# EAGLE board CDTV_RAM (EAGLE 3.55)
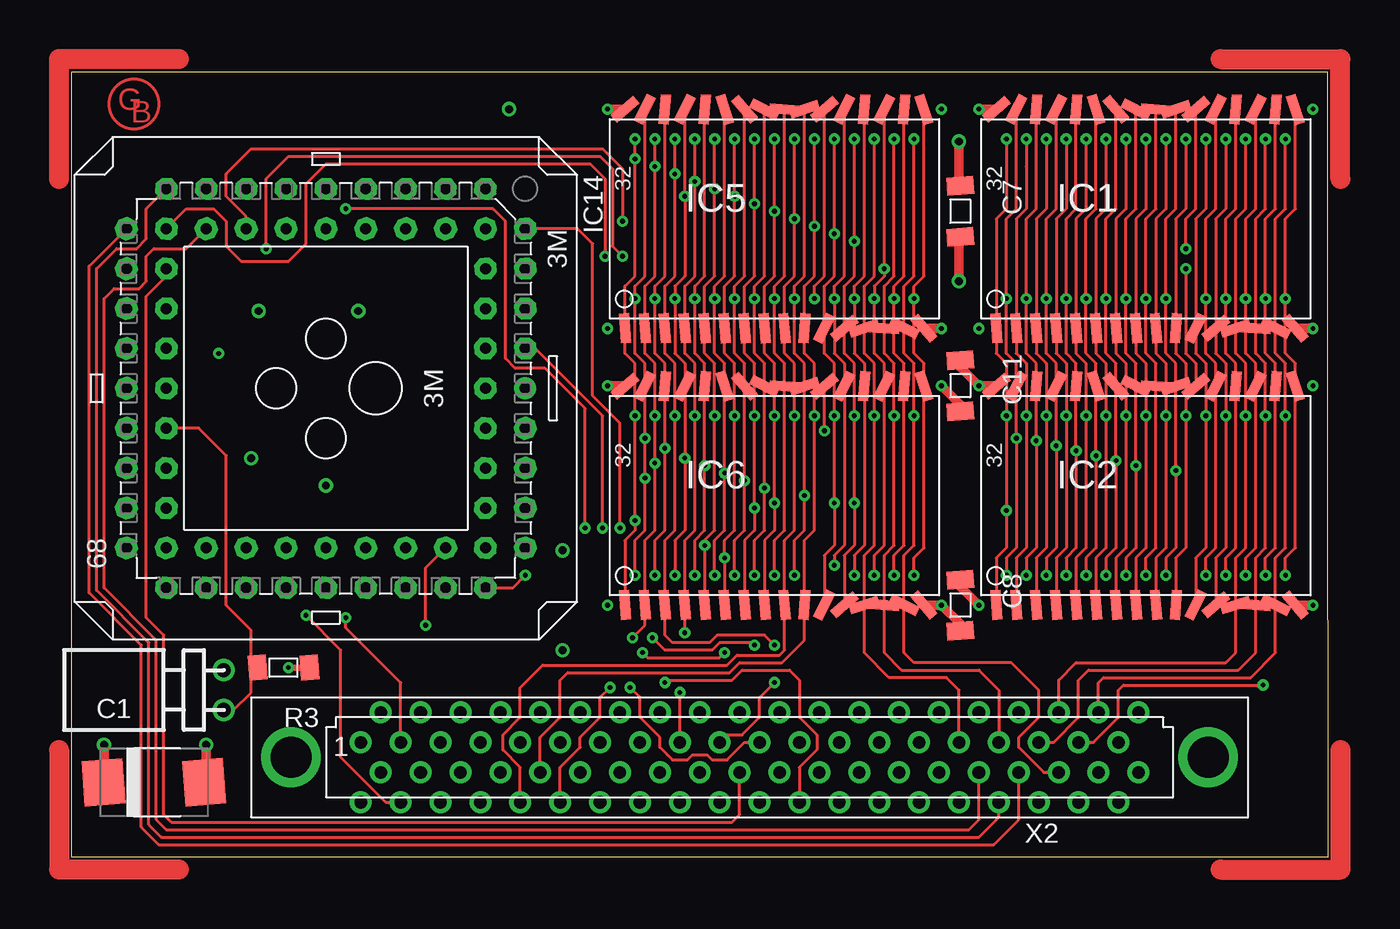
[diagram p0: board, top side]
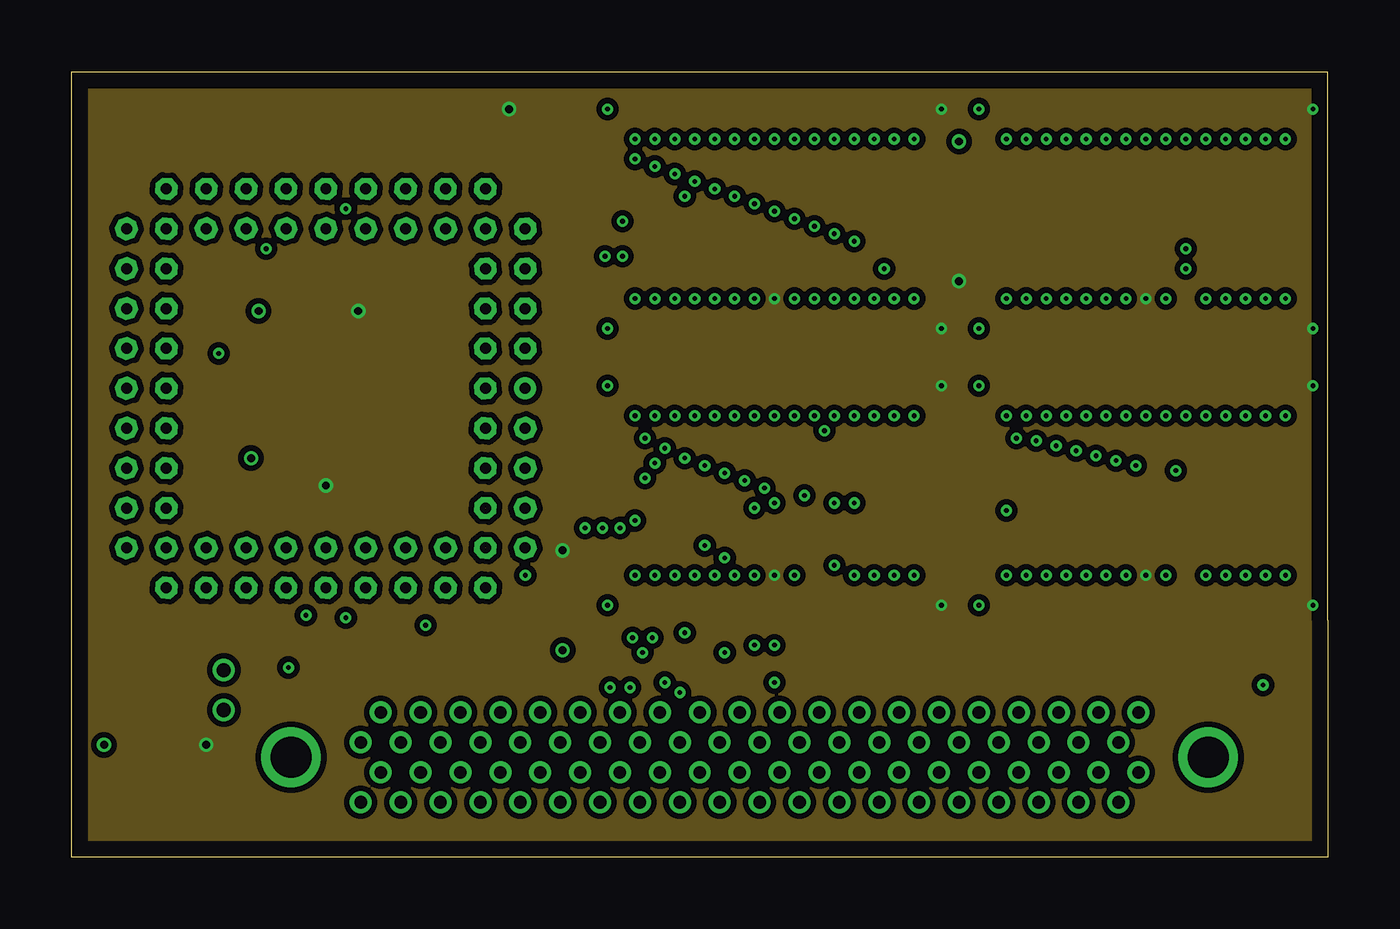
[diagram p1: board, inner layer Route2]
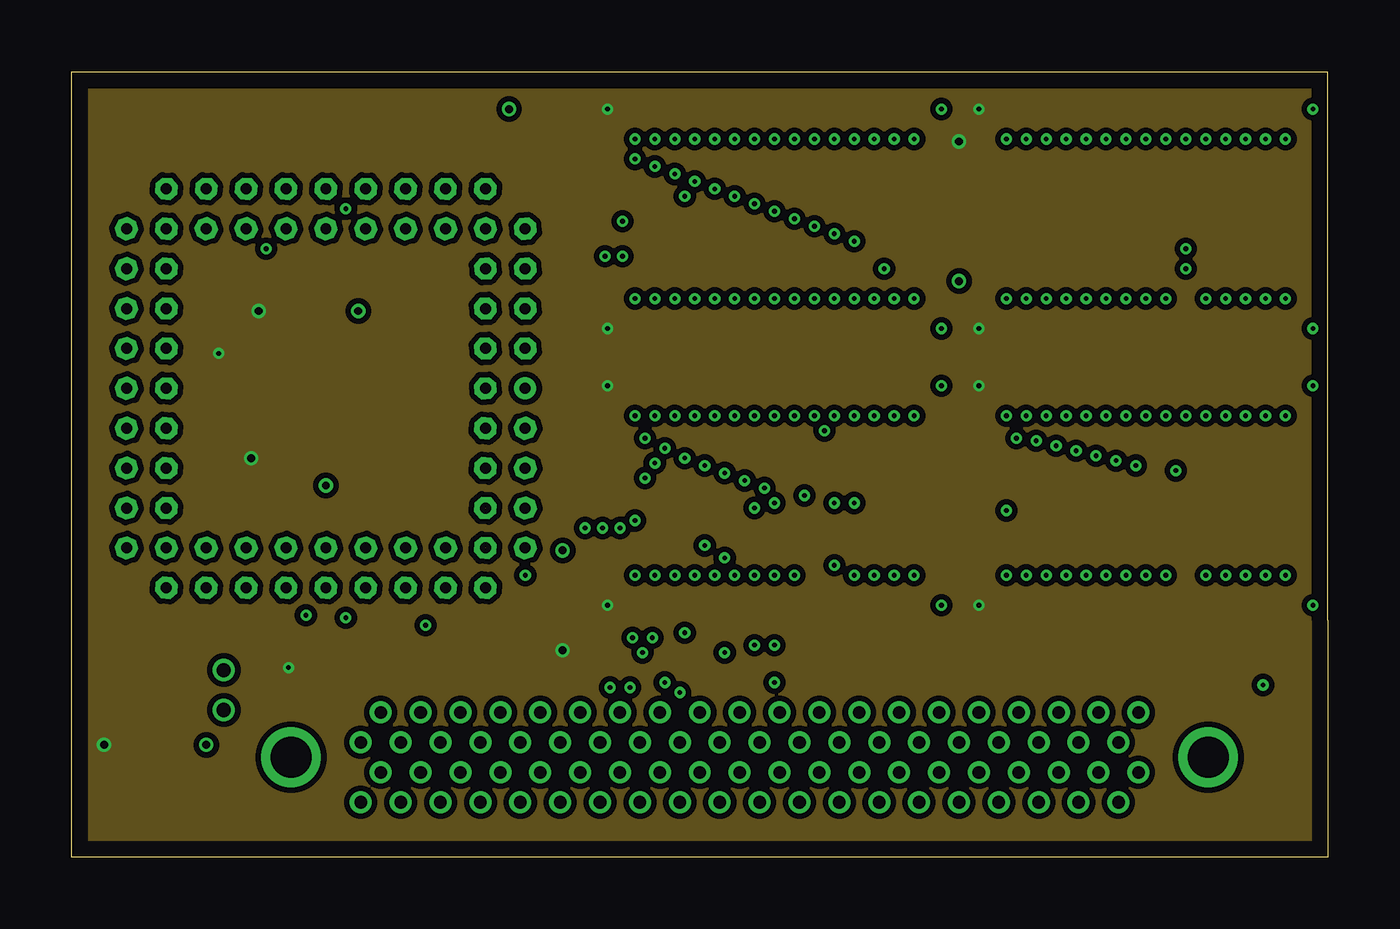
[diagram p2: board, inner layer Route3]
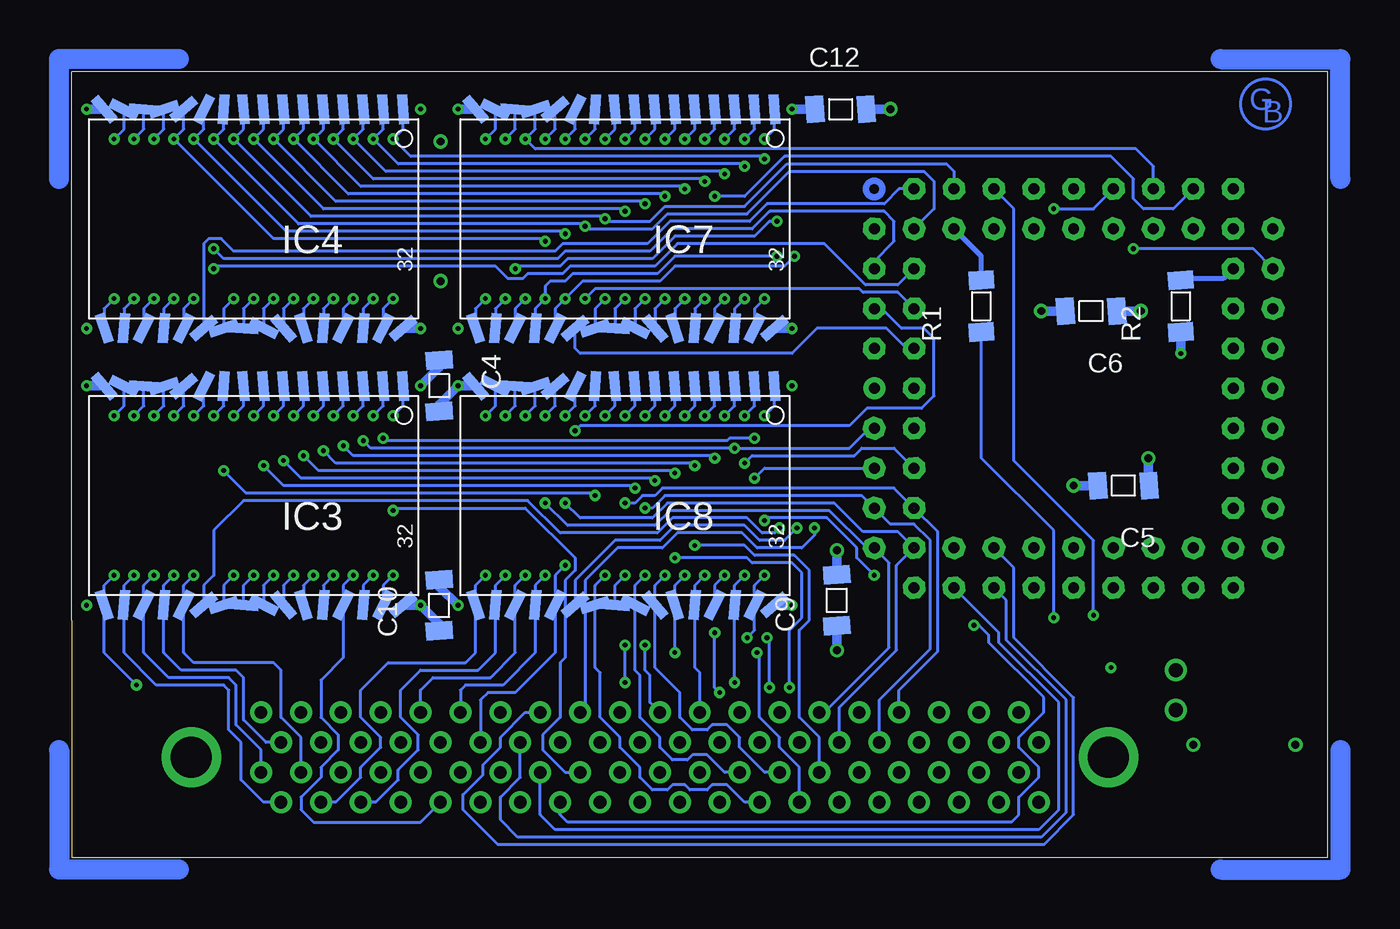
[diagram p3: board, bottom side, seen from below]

Size 80.01 x 50.01 mm. Coordinates in mm from the lower left corner, seen from the top.
Outline: 80.01,15.08 80.01,0 0,0 0,50.01 80.01,50.01 80.01,15.08
Copper layers used: Top, Route2, Route3, Bottom

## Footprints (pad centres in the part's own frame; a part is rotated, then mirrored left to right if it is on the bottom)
43 = smd 2.6 x 2.9 rotated 4.4:  3.207,0 | smd 2.6 x 2.9 rotated 4.3:  -3.207,0
06 = smd 1.143 x 1.702 rotated 4.4:  1.632,0 | smd 1.143 x 1.702 rotated 4.3:  -1.632,0
J32/5 = smd 0.635 x 1.905 rotated 49.5:  -9.525,6.966 | smd 0.635 x 1.905 rotated 27:  -8.255,6.966 | smd 0.635 x 1.905 rotated 4.5:  -6.985,6.966;  -6.985,-6.966 | smd 0.635 x 1.905 rotated 206.9:  -5.715,6.966 | smd 0.635 x 1.905 rotated 184.4:  -4.445,6.966 | smd 0.635 x 1.905 rotated 26.9:  4.445,6.966 | smd 0.635 x 1.905 rotated 49.4:  3.175,6.966 | smd 0.635 x 1.905 rotated 71.9:  1.905,6.966 | smd 0.635 x 1.905 rotated 94.4:  0.635,6.966 | smd 0.635 x 1.905 rotated 49.3:  4.445,-6.966 | smd 0.635 x 1.905 rotated 26.8:  3.175,-6.966 | smd 0.635 x 1.905 rotated 4.3:  1.905,-6.966;  -9.525,-6.966 | smd 0.635 x 1.905 rotated 5:  0.635,-6.966 | smd 0.635 x 1.905 rotated 4.7:  -4.445,-6.966;  -3.175,-6.966 | smd 0.635 x 1.905 rotated 4.6:  -5.715,-6.966 | smd 0.635 x 1.905 rotated 4.4:  -8.255,-6.966;  5.715,6.966 | smd 0.635 x 1.905 rotated 71.8:  5.715,-6.966 | smd 0.635 x 1.905 rotated 161.9:  -3.175,6.966 | smd 0.635 x 1.905 rotated 116.9:  -0.635,6.966 | smd 0.635 x 1.905 rotated 4.9:  -0.635,-6.966 | smd 0.635 x 1.905 rotated 139.4:  -1.905,6.966 | smd 0.635 x 1.905 rotated 4.8:  -1.905,-6.966 | smd 0.635 x 1.905 rotated 94.3:  6.985,-6.966 | smd 0.635 x 1.905 rotated 206.8:  6.985,6.966 | smd 0.635 x 1.905 rotated 116.8:  8.255,-6.966 | smd 0.635 x 1.905 rotated 139.3:  9.525,-6.966 | smd 0.635 x 1.905 rotated 184.3:  8.255,6.966 | smd 0.635 x 1.905 rotated 161.8:  9.525,6.966
CC68 = drill 0.7 pad 1.4 round:  0,12.7 | drill 0.7 pad 1.4 octagon:  0,10.16;  -2.54,12.7;  -2.54,10.16;  -5.08,12.7;  -5.08,10.16;  -7.62,12.7;  -7.62,10.16;  -10.16,12.7;  -12.7,10.16;  -10.16,10.16;  -12.7,7.62;  -10.16,7.62;  -12.7,5.08;  -10.16,5.08;  -12.7,2.54;  -10.16,2.54;  -12.7,0;  -10.16,0;  -12.7,-2.54;  -10.16,-2.54;  -12.7,-5.08;  -10.16,-5.08;  -12.7,-7.62;  -10.16,-7.62;  -12.7,-10.16;  -10.16,-12.7;  -10.16,-10.16;  -7.62,-12.7;  -7.62,-10.16;  -5.08,-12.7;  -5.08,-10.16;  -2.54,-12.7;  -2.54,-10.16;  0,-12.7;  0,-10.16;  2.54,-12.7;  2.54,-10.16;  5.08,-12.7;  5.08,-10.16;  7.62,-12.7;  7.62,-10.16;  10.16,-12.7;  12.7,-10.16;  10.16,-10.16;  12.7,-7.62;  10.16,-7.62;  12.7,-5.08;  10.16,-5.08;  12.7,-2.54;  10.16,-2.54;  12.7,0;  10.16,0;  12.7,2.54;  10.16,2.54;  12.7,5.08;  10.16,5.08;  12.7,7.62;  10.16,7.62;  12.7,10.16;  10.16,12.7;  10.16,10.16;  7.62,12.7;  7.62,10.16;  5.08,12.7;  5.08,10.16;  2.54,12.7;  2.54,10.16
04 = smd 1.16 x 1.6 rotated 4.4:  1.651,0 | smd 1.16 x 1.6 rotated 4.3:  -1.651,0
UECK-J = drill 0.9 pad 1.422 round:  -1.27,5.08;  1.27,5.08
TV-80 = drill 2.6 pad 3.8 round: 1 29.21,0; 2 -29.21,0 | drill 0.8 pad 1.4 round:  24.765,-0.953;  24.765,2.857;  23.495,-2.857;  23.495,0.953;  22.225,-0.953;  22.225,2.857;  20.955,-2.857;  20.955,0.953;  19.685,-0.953;  19.685,2.857;  18.415,-2.857;  18.415,0.953;  17.145,-0.953;  17.145,2.857;  15.875,-2.857;  15.875,0.953;  14.605,-0.953;  14.605,2.857;  13.335,-2.857;  13.335,0.953;  12.065,-0.953;  12.065,2.857;  10.795,-2.857;  10.795,0.953;  9.525,-0.953;  9.525,2.857;  8.255,-2.857;  8.255,0.953;  6.985,-0.953;  6.985,2.857;  5.715,-2.857;  5.715,0.953;  4.445,-0.953;  4.445,2.857;  3.175,-2.857;  3.175,0.953;  1.905,-0.953;  1.905,2.857;  0.635,-2.857;  0.635,0.953;  -0.635,-0.953;  -0.635,2.857;  -1.905,-2.857;  -1.905,0.953;  -3.175,-0.953;  -3.175,2.857;  -4.445,-2.857;  -4.445,0.953;  -5.715,-0.953;  -5.715,2.857;  -6.985,-2.857;  -6.985,0.953;  -8.255,-0.953;  -8.255,2.857;  -9.525,-2.857;  -9.525,0.953;  -10.795,-0.953;  -10.795,2.857;  -12.065,-2.857;  -12.065,0.953;  -13.335,-0.953;  -13.335,2.857;  -14.605,-2.857;  -14.605,0.953;  -15.875,-0.953;  -15.875,2.857;  -17.145,-2.857;  -17.145,0.953;  -18.415,-0.953;  -18.415,2.857;  -19.685,-2.857;  -19.685,0.953;  -20.955,-0.953;  -20.955,2.857;  -22.225,-2.857;  -22.225,0.953;  -23.495,-0.953;  -23.495,2.857;  -24.765,-2.857;  -24.765,0.953

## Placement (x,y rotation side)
C1  47uF  [43]  5.24,4.76 0 top
C4  100nF  [06]  56.59,30 270 bottom
C5  100nF  [06]  13.02,23.65 180 bottom
C6  100nF  [06]  15.08,34.77 180 bottom
C7  100nF  [06]  56.59,41.12 270 top
C8  100nF  [06]  56.59,16.03 270 top
C9  100nF  [06]  31.27,16.35 90 bottom
C10  100nF  [06]  56.59,16.03 90 bottom
C11  100nF  [06]  56.59,30 270 top
C12  100nF  [06]  31.04,47.63 0 bottom
IC1  628512  [J32/5]  68.42,40.64 0 top
IC2  628512  [J32/5]  68.42,23.02 0 top
IC3  628512  [J32/5]  68.42,23.02 180 bottom
IC4  628512  [J32/5]  68.42,40.64 180 bottom
IC5  628512  [J32/5]  44.77,40.64 0 top
IC6  628512  [J32/5]  44.77,23.02 0 top
IC7  628512  [J32/5]  44.77,40.64 180 bottom
IC8  628512  [J32/5]  44.77,23.02 180 bottom
IC14  LSI1024  [CC68]  16.19,29.85 270 top
R1  332R  [04]  22.07,35.08 90 bottom
R2  4k7  [04]  9.37,35.08 90 bottom
R3  4k7  [04]  13.49,12.07 180 top
S1  JUM-BR  [UECK-J]  4.6,10.64 270 top
U$2  []  3.97,47.94 0 top
U$3  [LO-2]  80.17,-0.16 180 top
U$4  [LO-2]  -0.16,-0.16 90 top
U$5  [LO-2]  80.17,50.16 270 top
U$6  []  3.97,47.94 0 bottom
U$9  [LO-2]  -0.16,50.17 0 top
X2  CDTV-80  [TV-80]  43.18,6.35 180 top

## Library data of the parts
C1 C4-C12 R1-R3 = SMD
IC1-IC8 = SMD-IC
IC14 = DIL-IC
S1 X2 = Stecker
U$2-U$6 U$9 = MARKS

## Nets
A1: IC1. IC2. IC3. IC4. IC5. IC6. IC7. IC8. IC14. X2.
A2: IC1. IC2. IC3. IC4. IC5. IC6. IC7. IC8. IC14. X2.
A3: IC1. IC2. IC3. IC4. IC5. IC6. IC7. IC8. IC14. X2.
A4: IC1. IC2. IC3. IC4. IC5. IC6. IC7. IC8. IC14. X2.
A5: IC1. IC2. IC3. IC4. IC5. IC6. IC7. IC8. IC14. X2.
A6: IC1. IC2. IC3. IC4. IC5. IC6. IC7. IC8. IC14. X2.
A7: IC1. IC2. IC3. IC4. IC5. IC6. IC7. IC8. X2.
A8: IC1. IC2. IC3. IC4. IC5. IC6. IC7. IC8. X2.
A9: IC1. IC2. IC3. IC4. IC5. IC6. IC7. IC8. X2.
A10: IC1. IC2. IC3. IC4. IC5. IC6. IC7. IC8. X2.
A11: IC1. IC2. IC3. IC4. IC5. IC6. IC7. IC8. X2.
A12: IC1. IC2. IC3. IC4. IC5. IC6. IC7. IC8. X2.
A13: IC1. IC2. IC3. IC4. IC5. IC6. IC7. IC8. X2.
A14: IC1. IC2. IC3. IC4. IC5. IC6. IC7. IC8. X2.
A15: IC1. IC2. IC3. IC4. IC5. IC6. IC7. IC8. X2.
A16: IC1. IC2. IC3. IC4. IC5. IC6. IC7. IC8. IC14. X2.
A17: IC1. IC2. IC3. IC4. IC5. IC6. IC7. IC8. IC14. X2.
A18: IC1. IC2. IC3. IC4. IC5. IC6. IC7. IC8. IC14. X2.
A19: IC1. IC2. IC3. IC4. IC5. IC6. IC7. IC8. IC14. X2.
A20: IC14. X2.
A21: IC14. X2.
A22: IC14. X2.
A23: IC14. X2.
AS: IC14. X2.
BERR: IC14. R2. X2.
CE0: IC1. IC14.
CE1: IC2. IC14.
CE2: IC3. IC14.
CE3: IC4. IC14.
CE4: IC5. IC14.
CE5: IC6. IC14.
CE6: IC7. IC14.
CE7: IC8. IC14.
CONFIN: IC14. X2.
CONFOUT: IC14. R1.
D0: IC1. IC2. IC3. IC4. X2.
D1: IC1. IC2. IC3. IC4. X2.
D2: IC1. IC2. IC3. IC4. X2.
D3: IC1. IC2. IC3. IC4. X2.
D4: IC1. IC2. IC3. IC4. X2.
D5: IC1. IC2. IC3. IC4. X2.
D6: IC1. IC2. IC3. IC4. X2.
D7: IC1. IC2. IC3. IC4. X2.
D8: IC5. IC6. IC7. IC8. X2.
D9: IC5. IC6. IC7. IC8. X2.
D10: IC5. IC6. IC7. IC8. X2.
D11: IC5. IC6. IC7. IC8. X2.
D12: IC5. IC6. IC7. IC8. IC14. X2.
D13: IC5. IC6. IC7. IC8. IC14. X2.
D14: IC5. IC6. IC7. IC8. IC14. X2.
D15: IC5. IC6. IC7. IC8. IC14. X2.
GND: C1. C4. C5. C6. C7. C8. C9. C10. C11. C12. IC1. IC2. IC3. IC4. IC5. IC6. IC7. IC8. IC14. S1. X2.
LDS: IC14. X2.
N$1: R1. X2.
OE: IC14.
RAMEN: IC14. R3. S1.
RST: IC14. X2.
RW: IC1. IC2. IC3. IC4. IC5. IC6. IC7. IC8. IC14. X2.
UDS: IC14. X2.
VCC: C1. C4. C5. C6. C7. C8. C9. C10. C11. C12. IC1. IC2. IC3. IC4. IC5. IC6. IC7. IC8. IC14. R2. R3. X2.

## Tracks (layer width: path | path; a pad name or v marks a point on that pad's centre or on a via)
A1  (via drill 0.3 pad 0.6)
  Top 0.2: v73.5,45.72 73.5,41.28 72.87,40.64 72.87,33.67 72.87,32.07 73.5,31.43 v73.5,28.1 73.5,19.69 72.87,19.05 72.87,16.05 | 49.85,36.99 49.21,36.35 49.21,33.67 49.21,32.07 49.85,31.43 v49.85,28.1 49.85,27.94 | 49.21,16.05 49.21,19.21 49.85,19.84 | v49.85,45.72 | v49.85,45.72 v49.85,39.21 49.85,36.99 | 49.85,36.99 | 49.85,27.94 | 49.85,27.94 v49.85,22.54 49.85,19.84 | 49.85,19.84
  Bottom 0.2: 72.87,47.61 72.87,46.36 v73.5,45.72 67.15,39.37 50.01,39.37 v49.85,39.21 | 72.87,29.99 72.87,28.73 v73.5,28.1 | 49.21,47.61 49.21,46.36 v49.85,45.72 | 49.21,29.99 49.21,28.73 v49.85,28.1 | 28.89,19.69 29.37,19.69 31.75,22.07 41.91,22.07 42.86,21.11 48.42,21.11 v49.85,22.54 | 32.38,9.21 32.07,9.21 27.94,13.34 27.94,18.73 28.89,19.69 | 28.89,19.69 | 28.89,19.69 | 28.89,19.69
A2  (via drill 0.3 pad 0.6)  (1 unrouted)
  Top 0.2: v72.23,45.72 72.23,41.28 71.6,40.64 71.6,33.67 71.6,32.07 72.23,31.43 v72.23,28.1 72.23,19.69 71.6,19.05 71.6,16.05 | 48.58,36.99 47.94,36.35 47.94,33.67 47.94,32.07 48.58,31.43 v48.58,28.1 | 47.94,16.05 47.94,19.21 48.58,19.84 | v48.58,45.72 | v48.58,45.72 v48.58,39.69 48.58,36.99 | 48.58,36.99 | v48.58,28.1 | v48.58,28.1 v48.58,22.54 48.58,19.84 | 48.58,19.84
  Bottom 0.2: 71.6,47.61 71.6,46.36 v72.23,45.72 66.36,39.85 48.74,39.85 v48.58,39.69 | 71.6,29.99 71.6,28.73 v72.23,28.1 | 47.94,47.61 47.94,46.36 v48.58,45.72 | 47.94,29.99 47.94,28.73 v48.58,28.1 | 26.35,19.69 27.38,20.72 29.61,20.72 31.43,22.54 42.07,22.54 43.02,21.59 47.62,21.59 v48.58,22.54 | 31.11,7.3 31.11,9.53 27.46,13.18 27.46,18.57 26.35,19.69
A3  (via drill 0.3 pad 0.6)
  Top 0.2: v70.96,45.72 70.96,41.28 70.33,40.64 70.33,33.67 70.33,32.07 70.96,31.43 v70.96,28.1 70.96,19.69 70.33,19.05 70.33,16.05 | 47.31,36.99 46.67,36.35 46.67,33.67 46.67,32.07 47.31,31.43 v47.31,28.1 47.31,20.8 46.67,20.16 46.67,16.05 46.67,13.81 45.24,12.38 42.54,12.38 41.91,11.75 31.59,11.75 31.11,11.27 31.11,8.89 29.84,7.62 29.84,5.4 | v47.31,45.72 | v47.31,45.72 v47.31,40.16 47.31,36.99 | 47.31,36.99
  Bottom 0.2: 70.33,47.61 70.33,46.36 v70.96,45.72 65.56,40.32 47.47,40.32 v47.31,40.16 47.15,40.01 43.02,40.01 42.07,40.96 36.99,40.96 34.29,43.66 25.72,43.66 25.08,43.02 25.08,41.28 26.35,40.01 | 70.33,29.99 70.33,28.73 v70.96,28.1 | 46.67,47.61 46.67,46.36 v47.31,45.72 | 46.67,29.99 46.67,28.73 v47.31,28.1 | 26.35,40.01 | 26.35,40.01
A4  (via drill 0.3 pad 0.6)
  Top 0.2: v69.69,45.72 69.69,41.28 69.06,40.64 69.06,33.67 69.06,32.07 69.69,31.43 v69.69,28.1 69.69,19.69 69.06,19.05 69.06,16.05 | v46.04,45.72 | v46.04,45.72 v46.04,40.64 46.04,36.99 45.4,36.35 45.4,33.67 45.4,32.07 46.04,31.43 v46.04,28.1 46.04,20.8 45.4,20.16 45.4,16.05 45.4,13.18 45.08,12.86 42.39,12.86 41.75,12.22 30,12.22 28.57,10.8 28.57,8.89 27.46,7.78 27.46,6.83 28.57,5.72 28.57,3.49
  Bottom 0.2: 69.06,47.61 69.06,46.36 v69.69,45.72 64.77,40.8 46.2,40.8 v46.04,40.64 45.88,40.48 43.18,40.48 42.23,41.43 37.15,41.43 34.45,44.13 24.29,44.13 23.81,43.66 23.81,42.55 | 69.06,29.99 69.06,28.73 v69.69,28.1 | 45.4,47.61 45.4,46.36 v46.04,45.72 | 45.4,29.99 45.4,28.73 v46.04,28.1 | 23.81,42.55 | 23.81,42.55
A5  (via drill 0.3 pad 0.6)  (1 unrouted)
  Top 0.2: v68.42,45.72 68.42,41.28 67.79,40.64 67.79,33.67 67.79,32.07 68.42,31.43 v68.42,28.1 68.42,19.69 67.79,19.05 67.79,16.05 | 44.77,36.99 44.13,36.35 44.13,33.67 44.13,32.07 44.77,31.43 v44.77,28.1 v44.77,22.54 44.77,20.8 44.13,20.16 44.13,16.05 | v44.77,45.72 | v44.77,45.72 v44.77,41.12 44.77,36.99 | 44.77,36.99
  Bottom 0.2: 67.79,47.61 67.79,46.36 v68.42,45.72 63.98,41.28 44.93,41.28 v44.77,41.12 | 67.79,29.99 67.79,28.73 v68.42,28.1 | 44.13,47.61 44.13,46.36 v44.77,45.72 | 44.13,29.99 44.13,28.73 v44.77,28.1 | 26.35,22.23 27.62,23.5 42.39,23.5 42.86,23.02 43.66,23.02 44.13,22.54 v44.77,22.54 | 26.35,22.23 24.84,20.72 24.84,13.1 27.3,10.64 27.3,9.21 | 27.3,9.21
A6  (via drill 0.3 pad 0.6)
  Top 0.2: v67.15,45.72 67.15,41.28 66.52,40.64 66.52,33.67 66.52,32.07 67.15,31.43 v67.15,28.1 67.15,19.69 66.52,19.05 66.52,16.05 | 43.5,36.99 42.86,36.35 42.86,33.67 42.86,32.07 43.5,31.43 v43.5,28.1 43.5,27.94 | 42.86,16.05 42.86,20.16 43.5,20.8 | v43.5,45.72 | v43.5,45.72 v43.5,41.59 43.5,36.99 | 43.5,36.99 | 43.5,27.94 | 43.5,27.94 v43.5,22.23 43.5,20.8 | 43.5,20.8
  Bottom 0.2: 66.52,47.61 66.52,46.36 v67.15,45.72 63.18,41.75 43.66,41.75 v43.5,41.59 | 66.52,29.99 66.52,28.73 v67.15,28.1 | 42.86,47.61 42.86,46.36 v43.5,45.72 | 42.86,29.99 42.86,28.73 v43.5,28.1 | 28.57,7.3 | 28.57,7.3 28.57,10 25.32,13.26 25.32,20.16 26.35,21.19 27.86,21.19 28.89,22.23 29.69,23.02 42.23,23.02 43.02,22.23 v43.5,22.23
A7  (via drill 0.3 pad 0.6)
  Top 0.2: v65.88,45.72 65.88,41.28 65.25,40.64 65.25,33.67 65.25,32.07 65.88,31.43 v65.88,28.1 65.88,19.69 65.25,19.05 65.25,16.05 | 42.23,36.99 41.59,36.35 41.59,33.67 41.59,32.07 42.23,31.43 v42.23,28.1 42.23,20.8 41.59,20.16 v41.59,19.05 41.59,16.03 | 41.59,16.03 | 41.59,16.03 41.59,16.05 | 42.23,36.99 | 42.23,36.99 v42.23,42.07 v42.23,45.72 | v42.23,45.72 | v34.29,10.8 33.65,10.16 33.65,8.89 32.38,7.62 32.38,6.99 31.11,5.72 31.11,3.49 | 31.11,3.49 | 41.59,16.03
  Bottom 0.2: 65.25,47.61 65.25,46.36 v65.88,45.72 62.39,42.23 42.39,42.23 v42.23,42.07 | 65.25,29.99 65.25,28.73 v65.88,28.1 | 41.59,47.61 41.59,46.36 v42.23,45.72 | 41.59,29.99 41.59,28.73 v42.23,28.1 | v34.29,10.8 34.29,14.45 33.5,15.24 33.5,18.1 34.13,18.73 36.67,18.73 36.99,19.05 v41.59,19.05
A8  (via drill 0.3 pad 0.6)
  Top 0.2: v64.61,45.72 64.61,41.28 63.98,40.64 63.98,33.67 63.98,32.07 64.61,31.43 v64.61,28.1 64.61,19.69 63.98,19.05 63.98,16.05 | 40.96,36.99 40.32,36.35 40.32,33.67 40.32,33.66 | 40.32,33.66 | 40.32,33.66 40.32,32.07 40.96,31.43 v40.96,28.1 40.96,20.8 40.32,20.16 v40.32,19.84 40.32,16.05 40.32,16.03 | 40.96,36.99 | 40.96,36.99 v40.96,42.55 v40.96,45.72 | v40.96,45.72
  Bottom 0.2: 63.98,47.61 63.98,46.36 v64.61,45.72 61.59,42.7 41.12,42.7 v40.96,42.55 | 63.98,29.99 63.98,28.73 v64.61,28.1 | 40.32,47.61 40.32,46.36 v40.96,45.72 | 40.32,29.99 40.32,28.73 v40.96,28.1 | 32.38,5.4 32.38,7.62 33.65,8.89 33.65,14.45 33.02,15.08 33.02,18.26 33.97,19.21 36.51,19.21 37.15,19.84 v40.32,19.84
A9  (via drill 0.3 pad 0.6)
  Top 0.2: 65.25,47.61 65.25,41.28 64.61,40.64 v64.61,35.56 64.61,32.07 65.25,31.43 65.25,29.99 65.25,29.85 v65.25,25.56 65.25,19.69 | 65.25,19.69 64.61,19.05 v64.61,17.94 | 41.59,47.61 41.59,36.99 40.96,36.35 v40.96,35.56 40.96,32.07 41.59,31.43 41.59,29.99 41.59,30 | 41.59,20.8 40.96,20.16 v40.96,17.94 | 65.25,19.69 | 41.59,20.8 | 41.59,20.8 v41.59,24.45 41.59,30 | 41.59,20.8 | 41.59,30 | 41.59,30 | 41.27,12.7 | 41.27,12.7 v41.59,13.02 | v36.35,13.02 36.67,12.7 41.27,12.7
  Bottom 0.2: 65.25,33.67 65.25,34.93 v64.61,35.56 | 65.25,16.05 65.25,17.3 v64.61,17.94 | 41.59,33.67 41.59,34.93 v40.96,35.56 | v40.96,17.94 41.59,17.3 41.59,16.05 41.59,16.03 | v41.59,24.45 41.75,24.61 64.29,24.61 v65.25,25.56 | 33.65,3.49 33.65,5.72 34.92,6.99 34.92,7.62 36.19,8.89 36.19,12.86 v36.35,13.02 | 41.59,16.03 | v41.59,13.02 41.59,16.03 | v36.35,13.02
A10  (via drill 0.3 pad 0.6)
  Top 0.2: 66.52,47.61 66.52,41.28 65.88,40.64 v65.88,35.56 65.88,32.07 66.52,31.43 66.52,29.99 66.52,29.85 v66.52,25.24 66.52,19.69 | 66.52,19.69 65.88,19.05 v65.88,17.94 | 42.86,47.61 42.86,36.99 42.23,36.35 v42.23,35.56 42.23,32.07 42.86,31.43 42.86,29.99 42.86,30 v42.86,23.97 42.86,20.8 42.23,20.16 v42.23,17.94 | 66.52,19.69
  Bottom 0.2: 66.52,33.67 66.52,34.93 v65.88,35.56 | 66.52,16.05 66.52,17.3 v65.88,17.94 | 42.86,33.67 42.86,34.93 v42.23,35.56 | v42.23,17.94 42.86,17.3 42.86,16.05 42.86,12.07 41.27,10.48 41.27,8.89 40.48,8.1 39.53,8.1 39.21,8.41 38.26,8.41 37.46,7.62 37.46,6.99 35.88,5.4 34.92,5.4 | v42.86,23.97 43.02,24.13 65.4,24.13 v66.52,25.24 | 34.92,5.4
A11  (via drill 0.3 pad 0.6)
  Top 0.2: 70.33,47.61 70.33,41.28 69.69,40.64 v69.69,35.56 69.69,32.07 70.33,31.43 70.33,29.99 70.33,30 v70.33,24.61 70.33,19.69 69.69,19.05 v69.69,17.94 | 46.67,47.61 46.67,36.99 46.04,36.35 v46.04,35.56 46.04,32.07 46.67,31.43 46.67,29.99 46.67,30 v46.67,23.02 46.67,20.8 46.04,20.16 v46.04,17.94
  Bottom 0.2: 70.33,33.67 70.33,34.93 v69.69,35.56 | 70.33,16.05 70.33,17.3 v69.69,17.94 | 46.67,33.67 46.67,34.93 v46.04,35.56 | v46.04,17.94 46.67,17.3 46.67,16.05 46.67,16.03 46.67,12.07 46.35,11.75 46.35,8.89 45.08,7.62 45.08,6.99 43.81,5.72 43.81,5.08 43.02,4.29 42.07,4.29 41.75,4.6 40.96,4.6 40.64,4.29 39.53,4.29 39.21,4.6 38.26,4.6 37.15,3.49 36.19,3.49 | v46.67,23.02 46.83,23.18 68.9,23.18 v70.33,24.61
A12  (via drill 0.3 pad 0.6)
  Top 0.2: 67.79,47.61 67.79,41.28 67.15,40.64 v67.15,35.56 67.15,32.07 67.79,31.43 67.79,29.99 67.79,30 v67.79,24.92 67.79,19.69 | 67.79,19.69 67.15,19.05 v67.15,17.94 | 44.13,47.61 44.13,36.99 43.5,36.35 v43.5,35.56 43.5,32.07 44.13,31.43 44.13,29.99 44.13,30 | 44.13,20.8 43.5,20.16 v43.5,17.94 | 67.79,19.69 | 44.13,20.8 | 44.13,20.8 v44.13,23.5 44.13,30 | 44.13,30
  Bottom 0.2: 67.79,33.67 67.79,34.93 v67.15,35.56 | 67.79,16.05 67.79,17.3 v67.15,17.94 | 44.13,33.67 44.13,34.93 v43.5,35.56 | v43.5,17.94 44.13,17.3 44.13,16.05 44.13,16.03 | v44.13,23.5 44.29,23.65 66.52,23.65 v67.79,24.92 | 37.46,5.4 38.42,5.4 39.53,6.51 40.48,6.51 40.8,6.19 41.75,6.19 42.54,6.99 42.54,7.62 43.81,8.89 43.81,11.59 44.13,11.91 44.13,16.03 | 44.13,16.03
A13  (via drill 0.3 pad 0.6)
  Top 0.2: 62.71,16.05 62.71,19.05 63.34,19.69 v63.34,28.1 63.34,31.43 62.71,32.07 62.71,33.67 62.71,40.64 63.34,41.28 63.34,41.91 v63.34,45.72 | 39.69,36.99 39.05,36.35 39.05,33.67 39.05,32.07 39.69,31.43 v39.69,28.1 39.69,20.8 39.05,20.16 39.05,16.03 | 39.05,16.03 | 39.05,16.03 39.05,16.05 | v39.69,45.72 | v39.69,45.72 v39.69,43.02 39.69,36.99 | 39.69,36.99 | v39.05,14.29 39.05,16.03 | 38.73,7.3 | 38.73,7.3 v38.73,10.48
  Bottom 0.2: 62.71,47.61 62.71,46.36 v63.34,45.72 60.8,43.18 39.85,43.18 v39.69,43.02 | 62.71,29.99 62.71,28.73 v63.34,28.1 | 39.05,47.61 39.05,46.36 v39.69,45.72 | 39.05,29.99 39.05,28.73 v39.69,28.1 | v39.05,14.29 39.05,10.8 v38.73,10.48
A14  (via drill 0.3 pad 0.6)
  Top 0.2: 63.98,47.61 63.98,41.28 63.34,40.64 v63.34,35.56 63.34,32.07 63.98,31.43 63.98,29.99 63.98,30 v63.98,25.88 63.98,19.69 | 63.98,19.69 63.34,19.05 v63.34,17.94 | 40.32,47.61 40.32,36.99 39.69,36.35 v39.69,35.56 39.69,32.07 40.32,31.43 40.32,29.99 40.32,30 v40.32,24.92 40.32,20.8 39.69,20.16 v39.69,17.94 | 63.98,19.69
  Bottom 0.2: 63.98,33.67 63.98,34.93 v63.34,35.56 | 63.98,16.05 63.98,17.3 v63.34,17.94 | 40.32,33.67 40.32,34.93 v39.69,35.56 | v39.69,17.94 40.32,17.3 40.32,16.05 40.32,12.07 40,11.75 40,9.21 | v40.32,24.92 40.48,25.08 63.18,25.08 v63.98,25.88 | 40,9.21
A15  (via drill 0.3 pad 0.6)
  Top 0.2: 62.07,41.28 61.44,40.64 61.44,33.67 61.44,32.07 62.07,31.43 v62.07,28.1 62.07,19.69 61.44,19.05 61.44,16.05 | 38.42,36.99 37.78,36.35 37.78,33.67 37.78,33.66 | 37.78,33.66 | 37.78,33.66 37.78,32.07 38.42,31.43 v38.42,28.1 38.42,20.8 37.78,20.16 37.78,16.05 37.78,14.13 38.26,13.65 40.64,13.65 41.12,14.13 44.13,14.13 v44.77,13.49 | v62.07,45.72 | 62.07,41.28 | v62.07,45.72 62.07,41.28 | v38.42,45.72 | v38.42,45.72 v38.42,43.5 38.42,36.99 | 38.42,36.99 | v44.77,11.11 43.81,10.16 43.81,8.89 42.7,7.78 41.75,7.78 41.27,7.3 | 41.27,7.3
  Bottom 0.2: 61.44,47.61 61.44,46.36 v62.07,45.72 60.01,43.66 38.58,43.66 v38.42,43.5 | 61.44,29.99 61.44,28.73 v62.07,28.1 | 37.78,47.61 37.78,46.36 v38.42,45.72 | 37.78,29.99 37.78,28.73 v38.42,28.1 | v44.77,11.11 v44.77,13.49
A16  (via drill 0.3 pad 0.6)
  Top 0.2: 60.17,41.28 59.53,40.64 v59.53,35.56 59.53,32.07 60.17,31.43 60.17,29.99 60.17,29.85 v60.17,26.67 60.17,19.69 | 60.17,19.69 59.53,19.05 v59.53,17.94 | 36.51,47.61 36.51,36.99 35.88,36.35 v35.88,35.56 35.88,32.07 36.51,31.43 36.51,29.99 | v35.88,17.94 35.88,20.16 36.51,20.8 | 36.51,30 | 36.51,29.99 36.51,30 | 60.17,47.61 60.17,47.63 60.17,41.28 | 60.17,41.28 | 60.17,19.69 | 36.51,29.85 | 36.51,29.85 36.51,29.99 | 36.51,29.85 v36.51,26.67 36.51,24.45 v36.51,24.13 36.51,20.8 | 36.51,20.8 | 36.51,20.8 | 36.51,20.8 | v43.5,13.49 43.34,13.65 41.27,13.65 40.8,13.18 37.78,13.18 v36.99,13.97 | v36.99,13.97
  Bottom 0.2: 60.17,33.67 60.17,34.93 v59.53,35.56 | 60.17,16.05 60.17,17.3 v59.53,17.94 | 36.51,33.67 36.51,34.93 v35.88,35.56 | v35.88,17.94 36.51,17.3 36.51,16.05 36.51,16.03 | 28.89,24.77 35.88,24.77 v36.51,24.13 | v36.51,26.67 | v36.51,26.67 38.1,26.67 38.26,26.51 60.01,26.51 v60.17,26.67 | 42.54,9.21 43.18,9.84 43.18,11.59 43.5,11.91 v43.5,13.49 | 36.51,16.03 | v36.99,13.97 36.51,14.45 36.51,16.03
A17  (via drill 0.3 pad 0.6)
  Top 0.2: 60.8,41.28 60.17,40.64 60.17,33.67 60.17,32.07 60.8,31.43 v60.8,28.1 60.8,19.69 60.17,19.05 60.17,16.05 | 37.15,36.99 36.51,36.35 36.51,33.67 36.51,33.66 | 36.51,33.66 | 36.51,33.66 36.51,32.07 37.15,31.43 v37.15,28.1 37.15,25.4 v37.15,25.08 37.15,20.8 | v37.15,45.72 | v37.15,45.72 v37.15,43.97 37.15,36.99 | 37.15,36.99 | v60.8,45.72 60.8,43.97 60.8,41.28 | 60.8,41.28 | 37.15,20.8 | 37.15,20.8 36.51,20.16 36.51,16.05 36.51,14.76 v35.72,13.97 | 43.81,7.3 42.86,7.3 41.75,6.19 40.8,6.19 40.48,6.51 39.53,6.51 39.21,6.19 38.26,6.19 37.94,6.51 | 37.94,6.51 | 37.94,6.51 37.46,6.99 37.46,7.62 36.19,8.89 36.19,10.16 v35.56,10.8
  Bottom 0.2: 60.17,47.61 60.17,46.36 v60.8,45.72 59.21,44.13 37.31,44.13 v37.15,43.97 | 60.17,29.99 60.17,28.73 v60.8,28.1 | 36.51,47.61 36.51,46.36 v37.15,45.72 | 36.51,29.99 36.51,28.73 v37.15,28.1 | v37.15,25.08 36.67,25.56 30.16,25.56 29.69,26.04 27.62,26.04 26.35,24.77 | 26.35,24.77 | 26.35,24.77 | v35.56,10.8 35.56,13.81 v35.72,13.97
A18  (via drill 0.3 pad 0.6)
  Top 0.2: 61.44,47.61 61.44,41.28 60.8,40.64 v60.8,35.56 60.8,32.07 61.44,31.43 61.44,29.99 61.44,30 v61.44,26.51 61.44,19.69 | 61.44,19.69 60.8,19.05 v60.8,17.94 | 37.78,47.61 37.78,36.99 37.15,36.35 v37.15,35.56 37.15,32.07 37.78,31.43 37.78,29.99 37.78,30 | v37.15,17.94 37.15,20.16 | 37.78,30 | 61.44,19.69 | 37.78,30 v37.78,26.04 37.78,20.8 37.15,20.16 | 37.15,20.16 | 46.35,3.49 | 46.35,3.49 46.35,5.72 47.47,6.83 47.47,7.78 46.35,8.89 46.35,11.27 45.72,11.91 42.7,11.91 42.07,11.27 37.94,11.27 v37.78,11.11
  Bottom 0.2: 61.44,33.67 61.44,34.93 v60.8,35.56 | 61.44,16.05 61.44,17.3 v60.8,17.94 | 37.78,33.67 37.78,34.93 v37.15,35.56 | v37.15,17.94 37.78,17.3 37.78,16.05 v37.78,11.11 | v61.44,26.51 60.96,26.04 v37.78,26.04 30.48,26.04 29.21,27.31 28.89,27.31
A19  (via drill 0.3 pad 0.6)
  Top 0.2: v59.53,28.1 59.53,31.43 58.9,32.07 58.9,33.67 58.9,40.64 59.53,41.28 | 58.9,16.05 58.9,19.05 59.53,19.69 | 35.88,36.99 35.24,36.35 35.24,33.66 | 35.24,33.66 | 35.24,33.66 35.24,33.67 35.24,32.07 35.88,31.43 v35.88,28.1 | 35.88,20.8 35.24,20.16 35.24,16.03 35.24,16.05 | v59.53,45.72 | 59.53,41.28 | v59.53,45.72 59.53,41.28 | 35.88,36.99 | 26.35,17.15 28.1,17.15 v28.89,17.94 | 35.88,20.8 | 35.88,20.8 | 35.88,20.8 v35.88,21.43 v35.88,28.1 | v35.88,28.1 | 35.88,36.99 v35.88,44.45 35.88,44.29 v35.88,45.72 | v59.53,28.1 | v59.53,28.1 v59.53,22.07 59.53,19.69 | 59.53,19.69
  Bottom 0.2: 58.9,29.99 58.9,28.73 v59.53,28.1 | 58.9,47.61 58.9,46.36 v59.53,45.72 58.42,44.61 36.04,44.61 v35.88,44.45 | 35.24,47.61 35.24,46.36 v35.88,45.72 | 35.24,29.99 35.24,28.73 v35.88,28.1 | v59.53,22.07 59.37,22.23 51.12,22.23 47.94,19.05 47.94,18.26 48.58,17.62 48.58,12.7 48.89,12.38 48.89,8.89 50.01,7.78 50.01,6.83 48.58,5.4 47.62,5.4 | 47.62,5.4 | v35.88,21.43 35.72,21.59 31.91,21.59 30,19.69 30,19.05 v28.89,17.94
A20  (via drill 0.3 pad 0.6)
  Top 0.2: v22.54,14.76 22.54,18.42 23.81,19.69 | 23.81,19.69
  Bottom 0.2: 48.89,3.49 48.89,2.7 48.42,2.22 20.16,2.22 19.68,2.7 19.68,3.81 18.41,5.08 18.41,5.72 19.68,6.99 19.68,7.62 18.1,9.21 18.1,10.16 21.59,13.65 21.59,14.13 22.22,14.76 v22.54,14.76
A21
  Bottom 0.2: 50.16,5.4 50.16,2.7 49.21,1.75 18.41,1.75 17.14,3.02 17.14,9.84 20.95,13.65 20.95,14.29 23.81,17.15 | 23.81,17.15
A22
  Bottom 0.2: 50.16,9.21 51.12,9.21 52.7,7.62 52.7,6.99 53.82,5.87 53.82,5.24 55.09,3.97 55.09,3.02 52.86,0.79 18.1,0.79 16.19,2.7 16.19,10.16 20,13.97 20,18.42 21.27,19.69
A23
  Bottom 0.2: 51.43,7.3 51.43,5.08 52.7,3.81 52.7,2.38 51.59,1.27 18.26,1.27 16.67,2.86 16.67,10 20.48,13.81 20.48,16.35 21.27,17.15 | 21.27,17.15 | 21.27,17.15
AS
  Top 0.2: 60.32,5.4 60.32,2.38 58.74,0.79 5.56,0.79 4.44,1.91 4.44,13.49 1.11,16.83 1.11,37.62 3.49,40.01 | 3.49,40.01
BERR
  Top 0.2: 42.54,5.4 42.54,2.7 42.07,2.22 6.35,2.22 5.87,2.7 5.87,14.13 4.76,15.24 4.76,35.72 6.03,36.99 6.03,37.47 | 6.03,37.47 | 6.03,37.47
  Bottom 0.305: 9.37,36.74 9.37,36.83 6.67,36.83 6.03,37.47 | 9.37,36.74
CE0  (via drill 0.3 pad 0.6)
  Top 0.2: 71.6,47.61 71.6,41.28 70.96,40.64 v70.96,38.74
  Bottom 0.2: 28.89,37.47 | 28.89,37.47 | 28.89,37.47 28.89,37.94 27.62,39.21 27.62,40.48 28.26,41.12 35.56,41.12 36.67,40.01 41.75,40.01 43.18,38.58 48.58,38.58 49.05,38.1 70.33,38.1 v70.96,38.74 | v70.96,38.74
CE1  (via drill 0.3 pad 0.6)
  Top 0.2: 71.6,29.99 71.6,31.43 70.96,32.07 v70.96,37.47
  Bottom 0.2: v70.96,37.47 70.8,37.62 53.02,37.62 52.23,36.83 51.28,36.83 50.96,37.15 48.74,37.15 48.26,37.62 42.86,37.62 41.43,39.05 32.07,39.05 29.45,36.43 27.38,36.43 26.35,37.47
CE2  (via drill 0.3 pad 0.6)
  Top 0.2: v34.92,20.96 34.92,27.62 33.18,29.37 33.18,39.05 32.23,40.01 28.89,40.01
  Bottom 0.2: 71.6,16.05 71.6,17.3 70.96,17.94 70.96,20.8 69.06,22.7 50.96,22.7 48.89,20.64 42.7,20.64 41.75,21.59 36.99,21.59 36.04,20.64 35.24,20.64 v34.92,20.96
CE3
  Bottom 0.2: 71.6,33.67 71.6,33.66 | 71.6,33.67 | 26.35,42.55 27.3,42.55 28.26,41.59 35.72,41.59 36.83,40.48 41.91,40.48 43.34,39.05 48.74,39.05 49.21,38.58 69.69,38.58 70.48,39.37 71.28,39.37 71.6,39.05 71.6,33.67
CE4  (via drill 0.3 pad 0.6)
  Top 0.2: 47.94,47.61 47.94,36.99 47.31,36.35 v47.31,35.56
  Bottom 0.2: v47.31,35.56 46.67,36.2 29.84,36.2 29.61,35.96 27.38,35.96 26.35,34.93 | 26.35,34.93 | 26.35,34.93
CE5  (via drill 0.3 pad 0.6)
  Top 0.2: v47.94,27.15 47.94,29.99
  Bottom 0.2: v47.94,27.15 47.62,27.46 35.4,27.46 | 28.89,34.93 28.42,34.93 27.15,33.66 25.72,33.66 25.08,33.02 25.08,29.37 25.88,28.58 29.37,28.58 30.48,27.46 35.4,27.46 | 35.4,27.46
CE6
  Bottom 0.2: 47.94,33.67 47.94,32.39 47.62,32.07 34.13,32.07 32.54,33.66 28.1,33.66 26.83,32.39 | 26.83,32.39 | 26.35,32.39 26.83,32.39
CE7  (via drill 0.3 pad 0.6)
  Top 0.2: 28.89,32.39 | 28.89,32.39 | v33.81,20.96 33.81,28.1 29.53,32.39 28.89,32.39
  Bottom 0.2: 47.94,16.05 47.94,17.62 45.4,20.16 42.54,20.16 41.59,21.11 37.15,21.11 36.19,20.16 34.61,20.16 v33.81,20.96
CONFIN  (via drill 0.3 pad 0.6)
  Top 0.2: v14.92,15.4 17.14,13.18 17.14,6.35 20,3.49 20.95,3.49
  Bottom 0.2: 21.27,42.55 20,41.28 20,25.24 14.92,20.16 v14.92,15.4
CONFOUT
  Bottom 0.305: 22.07,36.74 22.07,38.26 23.81,40.01
D0  (via drill 0.3 pad 0.6)
  Top 0.2: v76.04,45.72 76.04,41.28 75.41,40.64 75.41,33.67 75.41,32.07 76.04,31.43 v76.04,28.1 76.04,19.69 75.41,19.05 75.41,16.05 75.41,16.03 | 61.59,7.3 62.55,7.3 64.13,8.89 64.13,11.27 64.77,11.91 74.29,11.91 75.41,13.02 75.41,16.03 | 75.41,16.03
  Bottom 0.2: 75.41,47.61 75.41,46.36 v76.04,45.72 | 75.41,29.99 75.41,28.73 v76.04,28.1
D1  (via drill 0.3 pad 0.6)
  Top 0.2: v74.77,45.72 74.77,41.28 74.14,40.64 74.14,33.67 74.14,32.07 74.77,31.43 v74.77,28.1 74.77,19.69 74.14,19.05 74.14,16.05 74.14,13.02 73.5,12.38 63.98,12.38 62.86,11.27 62.86,9.21 | 62.86,9.21
  Bottom 0.2: 74.14,47.61 74.14,46.36 v74.77,45.72 | 74.14,29.99 74.14,28.73 v74.77,28.1
D2  (via drill 0.3 pad 0.6)
  Top 0.2: IC1. 77.95,41.28 77.31,40.64 v77.31,35.56 77.31,32.07 77.95,31.43 IC2. 77.95,19.69 77.31,19.05 v77.31,17.94 | 64.13,7.3 65.09,7.3 66.67,8.89 66.67,10.64 66.99,10.95 v75.88,10.95
  Bottom 0.2: IC4. 77.95,34.93 v77.31,35.56 | v77.31,17.94 77.95,17.3 IC3. 77.95,13.02 v75.88,10.95
D3  (via drill 0.3 pad 0.6)
  Top 0.2: v77.31,45.72 77.31,41.28 76.68,40.64 76.68,33.67 76.68,32.07 77.31,31.43 v77.31,28.1 77.31,19.69 76.68,19.05 76.68,16.05 76.68,16.03 | 65.4,9.21 65.4,11.11 65.72,11.43 75.09,11.43 76.68,13.02 76.68,16.03 | 76.68,16.03
  Bottom 0.2: 76.68,47.61 76.68,46.36 v77.31,45.72 | 76.68,29.99 76.68,28.73 v77.31,28.1
D4  (via drill 0.3 pad 0.6)
  Top 0.2: 74.14,47.61 74.14,41.28 73.5,40.64 v73.5,35.56 73.5,32.07 74.14,31.43 74.14,29.99 74.14,19.69 73.5,19.05 v73.5,17.94
  Bottom 0.2: 74.14,33.67 74.14,34.93 v73.5,35.56 | v73.5,17.94 74.14,17.3 74.14,16.05 74.14,13.02 73.02,11.91 69.53,11.91 69.06,11.43 69.06,8.73 67.63,7.3 66.67,7.3
D5  (via drill 0.3 pad 0.6)
  Top 0.2: 75.41,47.61 75.41,41.28 74.77,40.64 v74.77,35.56 74.77,32.07 75.41,31.43 75.41,29.99 75.41,19.69 74.77,19.05 v74.77,17.94
  Bottom 0.2: 75.41,33.67 75.41,34.93 v74.77,35.56 | v74.77,17.94 75.41,17.3 75.41,16.05 75.41,13.02 73.82,11.43 70.01,11.43 69.53,10.95 69.53,8.41 67.94,6.83 X2.
D6  (via drill 0.3 pad 0.6)
  Top 0.2: 76.68,47.61 76.68,41.28 76.04,40.64 v76.04,35.56 76.04,32.07 76.68,31.43 76.68,29.99 76.68,19.69 76.04,19.05 v76.04,17.94
  Bottom 0.2: 76.68,33.67 76.68,34.93 v76.04,35.56 | 76.68,16.19 76.68,17.3 v76.04,17.94 | 66.67,3.49 67.79,3.49 69.21,4.92 69.21,7.3 70.01,8.1 70.01,10.64 70.33,10.95 74.61,10.95 76.68,13.02 76.68,16.19 | 76.68,16.19 76.68,16.05
D7  (via drill 0.3 pad 0.6)
  Top 0.2: 72.87,47.61 72.87,41.28 72.23,40.64 v72.23,35.56 72.23,32.07 72.87,31.43 72.87,29.99 72.87,19.69 72.23,19.05 v72.23,17.94
  Bottom 0.2: 72.87,33.67 72.87,34.93 v72.23,35.56 | v72.23,17.94 72.87,17.3 72.87,16.05 72.87,13.02 72.23,12.38 67.15,12.38 66.67,11.91 66.67,8.89 65.4,7.62 65.4,5.4
D8  (via drill 0.3 pad 0.6)
  Top 0.2: IC5. 54.29,36.99 53.66,36.35 v53.66,35.56 53.66,32.07 54.29,31.43 IC6. 54.29,19.69 53.66,19.05 v53.66,17.94
  Bottom 0.2: IC7. 54.29,34.93 v53.66,35.56 | IC8. 54.29,17.3 v53.66,17.94 | 54.31,16.03 54.29,16.03 54.29,13.02 54.93,12.38 59.85,12.38 61.59,10.64 61.59,8.89 60.32,7.62 60.32,6.99 61.59,5.72 61.59,5.08 63.18,3.49 64.13,3.49
  Bottom 0.61: 54.31,16.03 IC8.
D9  (via drill 0.3 pad 0.6)
  Top 0.2: v53.66,45.72 53.66,36.99 53.02,36.35 53.02,33.67 53.02,32.07 53.66,31.43 v53.66,28.1 53.66,19.84 53.02,19.21 53.02,16.05 53.02,16.03 | 53.02,16.03 | 53.02,16.03 53.02,13.02 53.66,12.38 59.85,12.38 61.59,10.64 61.59,8.89 60.32,7.62 60.32,6.99 61.91,5.4 62.86,5.4
  Bottom 0.2: 53.02,47.61 53.02,46.36 v53.66,45.72 | 53.02,29.99 53.02,28.73 v53.66,28.1
D10  (via drill 0.3 pad 0.6)
  Top 0.2: 53.02,47.61 53.02,36.99 52.39,36.35 v52.39,35.56 52.39,32.07 53.02,31.43 53.02,29.99 53.02,19.84 52.39,19.21 v52.39,17.94
  Bottom 0.2: 53.02,33.67 53.02,34.93 v52.39,35.56 | v52.39,17.94 53.02,17.3 53.02,16.05 53.02,16.03 | 53.02,16.03 | 53.02,16.03 53.02,13.02 54.13,11.91 57.78,11.91 59.05,10.64 59.05,8.89 57.94,7.78 57.94,6.83 59.21,5.56 59.21,4.92 60.64,3.49 61.59,3.49
D11  (via drill 0.3 pad 0.6)
  Top 0.2: v52.39,45.72 52.39,36.99 51.75,36.35 51.75,33.67 51.75,32.07 52.39,31.43 v52.39,28.1 52.39,19.84 51.75,19.21 51.75,16.05 51.75,16.03 51.75,13.02 52.86,11.91 57.78,11.91 59.05,10.64 59.05,7.3
  Bottom 0.2: 51.75,47.61 51.75,46.36 v52.39,45.72 | 51.75,29.99 51.75,28.73 v52.39,28.1
D12  (via drill 0.3 pad 0.6)  (1 unrouted)
  Top 0.2: 51.75,36.99 51.12,36.35 v51.12,35.56 51.12,32.07 51.75,31.43 51.75,29.99 51.75,19.84 51.12,19.21 v51.12,17.94 | 51.75,47.61 51.75,47.63 | 51.75,47.61 | 51.75,47.61 v51.75,37.47 51.75,36.99 | 51.75,36.99 | v35.08,40.48 35.08,43.82 33.81,45.09 11.43,45.09 9.84,43.5 9.84,42.07 11.11,40.8 11.11,40.01 | 11.11,40.01
  Bottom 0.2: 51.75,33.67 51.75,34.93 v51.12,35.56 | v51.12,17.94 51.75,17.3 51.75,16.05 51.75,16.03 | 57.78,9.21 57.78,10.64 56.99,11.43 53.34,11.43 51.75,13.02 51.75,16.03 | 51.75,16.03 | v51.75,37.47 51.59,37.62 48.89,37.62 48.42,38.1 43.02,38.1 41.59,39.53 36.51,39.53 35.56,40.48 v35.08,40.48
D13  (via drill 0.3 pad 0.6)  (1 unrouted)
  Top 0.2: v51.12,45.72 51.12,36.99 50.48,36.35 50.48,33.67 50.48,32.07 51.12,31.43 v51.12,28.1 51.12,19.84 50.48,19.21 50.48,16.05 50.48,16.03 | 56.51,7.3 56.51,10.64 55.72,11.43 52.07,11.43 50.48,13.02 50.48,16.03 | 50.48,16.03
  Bottom 0.2: 50.48,47.61 50.48,46.36 v51.12,45.72 | 50.48,29.99 50.48,28.73 v51.12,28.1 | v51.12,45.72 50.48,45.09 12.22,45.09 11.11,43.97 11.11,42.55 | 11.11,42.55
D14  (via drill 0.3 pad 0.6)
  Top 0.2: 50.48,47.61 50.48,36.99 49.85,36.35 v49.85,35.56 49.85,32.07 50.48,31.43 50.48,29.99 50.48,19.84 49.85,19.21 v49.85,17.94 | v35.08,38.26 34.45,38.89 34.45,43.82 33.65,44.61 13.81,44.61 12.38,43.18 v12.38,38.74
  Bottom 0.2: 50.48,33.67 50.48,34.93 v49.85,35.56 49.85,36.35 49.53,36.67 48.58,36.67 48.1,37.15 42.7,37.15 41.59,38.26 v35.08,38.26 | v49.85,17.94 50.48,17.3 50.48,16.05 50.48,13.02 52.55,10.95 54.93,10.95 55.24,10.64 55.24,9.21 | 55.24,9.21 | 3.49,37.47 4.76,38.74 v12.38,38.74 | 3.49,37.47
D15  (via drill 0.3 pad 0.6)
  Top 0.2: 49.21,47.61 49.21,36.99 48.58,36.35 v48.58,35.56 48.58,32.07 49.21,31.43 49.21,29.99 49.21,19.84 48.58,19.21 v48.58,18.57 | v33.97,38.26 33.97,43.18 33.02,44.13 16.19,44.13 14.92,42.86 14.92,39.05 13.81,37.94 10.79,37.94 9.84,38.89 9.84,40.48 9.05,41.28 7.3,41.28 6.03,40.01 | 6.03,40.01 | 6.03,40.01
  Bottom 0.2: 49.21,33.67 49.21,34.93 v48.58,35.56 47.47,36.67 42.54,36.67 41.59,37.62 34.61,37.62 v33.97,38.26 | v48.58,18.57 49.21,17.94 49.21,16.05 49.21,16.03 | 53.97,7.3 53.97,10 53.5,10.48 51.75,10.48 49.21,13.02 49.21,16.03 | 49.21,16.03
GND  (via drill 0.3 pad 0.6, 0.5 pad 0.9)
  Top 0.2: 69.06,47.61 69.06,41.28 68.42,40.64 v68.42,35.56 68.42,32.07 69.06,31.43 69.06,29.85 | v68.42,17.94 68.42,19.05 69.06,19.69 69.06,29.85 | 69.06,29.85 69.06,29.99 | 45.4,47.61 45.4,36.99 44.77,36.35 v44.77,35.56 44.77,32.07 45.4,31.43 45.4,30 | v44.77,17.94 44.77,20.16 45.4,20.8 45.4,29.99 45.4,30 | 45.4,30 | 45.4,30
  Top 0.61: IC7. 54.31,33.66 v55.4,33.66 | IC4. 77.97,33.66 v79.06,33.66 | IC3. 77.97,16.03 v79.06,16.03 | IC8. 54.31,16.03 v55.4,16.03 56.59,14.84 C10. | 8.45,4.76 8.57,4.89 v8.57,7.14 | 56.59,39.48 56.51,39.41 v56.51,36.67 | 56.59,28.37 56.59,28.81 v55.4,30
  Bottom 0.2: 69.06,33.67 69.06,34.93 v68.42,35.56 | 69.06,16.05 69.06,17.3 v68.42,17.94 | 45.4,33.67 45.4,34.93 v44.77,35.56 | 45.4,16.05 45.4,17.3 v44.77,17.94
  Bottom 0.406: 56.59,17.22 C8.
  Bottom 0.61: IC5. 54.31,47.63 v55.4,47.63 | IC6. 54.31,30 v55.4,30 56.59,28.81 56.59,28.37 | IC1. 77.96,47.63 v79.06,47.63 | IC2. 77.97,30 v79.06,30 | v55.4,16.03 56.59,17.22 | 56.59,28.37 56.59,28.34 | 56.59,28.37 | 16.71,34.77 v18.26,34.77 | 14.65,23.65 v16.19,23.65 | 29.4,47.63 | v27.86,47.63 29.4,47.63 | 31.27,17.98 v31.27,19.53 | C8.
  pour Route2 (isolate 0.356, no thermals): 0.64,49.37 0.64,0.64 79.38,0.64 79.37,49.37
LDS
  Top 0.2: 57.78,5.4 57.78,2.38 57.15,1.75 6.03,1.75 5.4,2.38 5.4,13.81 2.06,17.15 2.06,35.56 2.7,36.2 4.29,36.2 4.76,36.67 4.76,38.26 5.24,38.74 7.3,38.74 8.57,40.01 | 8.57,40.01 | 8.57,40.01
N$1  (via drill 0.3 pad 0.6)
  Top 0.2: v17.46,15.24 17.46,14.61 20.95,11.11 20.95,7.3 | 20.95,7.3
  Bottom 0.2: R1. 22.07,25.4 17.46,20.8 v17.46,15.24
RAMEN
  Top 0.2: 6.03,27.31 | 6.03,27.31 8.1,27.31 9.84,25.56 9.84,16.03 11.43,14.45 11.43,12.54 11.84,12.13 11.84,12.07 11.43,11.65 11.43,10.48 10.32,9.37 S1. | S1.
RST  (via drill 0.3 pad 0.6)
  Top 0.2: v32.7,20.96 32.7,28.58 32.23,29.05 30.16,31.12 28.26,31.12 27.62,31.75 27.62,40.48 26.83,41.28 v17.46,41.28
  Bottom 0.2: 47.62,9.21 47.31,9.53 47.31,17.62 45.24,19.69 42.39,19.69 41.43,20.64 37.31,20.64 36.35,19.69 33.5,19.69 32.7,20.48 v32.7,20.96 | 13.65,42.55 14.92,41.28 v17.46,41.28
RW  (via drill 0.3 pad 0.6)
  Top 0.2: 62.71,47.61 62.71,41.28 62.07,40.64 v62.07,35.56 62.07,32.07 62.71,31.43 62.71,29.99 62.71,29.85 v62.71,26.19 62.71,19.69 | 62.71,19.69 62.07,19.05 v62.07,17.94 | 39.05,36.99 38.42,36.35 v38.42,35.56 38.42,32.07 39.05,31.43 39.05,29.99 39.05,30 | v38.42,17.94 38.42,20.16 39.05,20.8 v39.05,25.4 39.05,30 | 62.71,19.69 | 39.05,30 | 39.05,47.61 39.05,47.63 | 39.05,47.61 | 39.05,47.61 v39.05,42.07 39.05,36.99 | 39.05,36.99
  Bottom 0.2: 62.71,33.67 62.71,34.93 v62.07,35.56 | v62.07,17.94 62.71,17.3 62.71,16.05 62.71,12.7 64.13,11.27 64.13,8.89 63.02,7.78 63.02,6.83 64.13,5.72 64.13,5.08 65.4,3.81 65.4,3.02 64.61,2.22 57.78,2.22 56.51,3.49 | 39.05,33.67 39.05,34.93 v38.42,35.56 | 39.05,16.05 39.05,17.3 v38.42,17.94 | v39.05,25.4 39.21,25.56 62.07,25.56 v62.71,26.19 | 8.57,42.55 9.84,41.28 11.75,41.28 12.38,41.91 12.38,43.18 13.81,44.61 34.61,44.61 37.15,42.07 v39.05,42.07
UDS
  Top 0.2: 59.05,3.49 59.05,2.54 57.78,1.27 5.71,1.27 4.92,2.06 4.92,13.65 1.59,16.99 1.59,37.47 2.86,38.74 4.13,38.74 4.76,39.37 4.76,41.28 6.03,42.55 | 6.03,42.55 | 6.03,42.55
VCC  (via drill 0.3 pad 0.6, 0.5 pad 0.9)  (1 unrouted)
  Top 0.406: R3. v13.81,12.07
  Top 0.61: 35.24,47.61 35.22,47.63 v34.13,47.63 | 35.24,29.99 35.22,30 v34.13,30 | 58.9,47.61 58.88,47.63 v57.78,47.63 | 58.9,29.99 58.88,30 v57.78,30 56.59,31.19 C11. 56.59,31.67 | C1. 2.06,4.79 v2.06,7.14 | C7. 56.51,42.83 v56.51,45.56 | C8. 56.59,17.23 v57.78,16.03
  Bottom 0.406: C10.
  Bottom 0.61: 35.24,33.67 35.22,33.66 v34.13,33.66 | 35.24,16.05 35.22,16.03 v34.13,16.03 | v57.78,33.66 58.9,33.67 | 58.9,16.05 58.88,16.03 v57.78,16.03 56.59,14.84 C10. | R2. v9.37,32.07 | C11. 56.59,31.19 v57.78,30 | C6. v11.91,34.77 | C5. 11.43,23.7 v11.43,25.4 | 32.62,47.63 | C12. 32.62,47.63 | 32.62,47.63 v34.13,47.63 | C9. v31.27,13.18
  pour Route3 (isolate 0.356, no thermals): 0.63,49.37 0.64,0.64 79.38,0.64 79.37,49.37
